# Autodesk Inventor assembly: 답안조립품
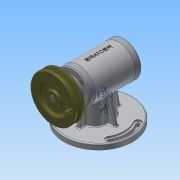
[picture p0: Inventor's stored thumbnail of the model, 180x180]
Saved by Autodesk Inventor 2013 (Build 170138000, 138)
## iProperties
Created: 2017-06
Part Number: 답안조립품
Document SubType Name: Assembly
Designer: Administrator
Mass: 1982.57 g
Surface Area: 1464.34 cm^2
Volume: 498.981 cm^3
Density: 3.97323 g/cm^3
Author: Administrator
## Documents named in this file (15)
- C:\Users\Administrator\Desktop\370608V1024\답안조립품.iam
- C:\Users\Administrator\Desktop\370608V1024\V-벨트풀리.ipt
- C:\Users\Administrator\Desktop\370608V1024\뒤커버.ipt
- C:\Users\Administrator\Desktop\370608V1024\멈춤나사 M3x8.ipt
- C:\Users\Administrator\Desktop\370608V1024\베어링 6201.ipt
- C:\Users\Administrator\Desktop\370608V1024\베어링 6202.ipt
- C:\Users\Administrator\Desktop\370608V1024\본체.ipt
- C:\Users\Administrator\Desktop\370608V1024\본체커버.ipt
- C:\Users\Administrator\Desktop\370608V1024\볼트 M3x0.5x8.ipt
- C:\Users\Administrator\Desktop\370608V1024\슬라이드.ipt
- C:\Users\Administrator\Desktop\370608V1024\앞커버.ipt
- C:\Users\Administrator\Desktop\370608V1024\오일실 12 22 7.ipt
- C:\Users\Administrator\Desktop\370608V1024\키 4 x 4 x 18.ipt
- C:\Users\Administrator\Desktop\370608V1024\편심축.ipt
- C:\Users\Administrator\Desktop\370608V1024\가변스프링.ipt
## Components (2 placed, 2 different names)
1. V-벨트풀리:1
2. 가변스프링:1
